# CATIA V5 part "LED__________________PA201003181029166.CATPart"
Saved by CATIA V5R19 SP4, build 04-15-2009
Part number: LED__________________PA201003181029166
Bounding box of the stored display mesh (mm): x -2.895 to 2.894, y -2.5 to 2.9, z -10 to 8.71
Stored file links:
  E:\CadInnWork\InWork\LED__________________PA201003181029166.CATPart
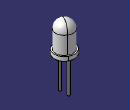
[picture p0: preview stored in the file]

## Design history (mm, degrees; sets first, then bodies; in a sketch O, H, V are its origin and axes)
Parameters
  Update = false
  PDM_version = "A"
  PDM_iteration = 1
  PDM_owner = "moren                    "
  PDM_comment = ""
  PDM_partnumber = "PA002170EA6A57201003181029160006"
Body1 (main body)
  Sketch1 on yz-plane, origin (0, 0, 0), H (0, 1, 0), V (0, 0, 1)
    axis line L1 (0, 64.2413) -> (0, -58.0007)
    point P1 (0, 64.2413)
    line L2 (0, 0) -> (2.9, 0)
    line L3 (2.9, 0) -> (2.9, 1.14)
    line L4 (2.9, 1.14) -> (2.5, 1.14)
    line L5 (2.5, 1.14) -> (2.5, 6.21)
    arc A1 centre (0, 6.21) radius 2.5 from (2.5, 6.21) to (0, 8.71) ccw
    point P7 (0, 6.21)
    point P8 (0, 8.71)
    "Radius" L3 L1 = 2.9
    "Radius" L5 L1 = 2.5
    length L3 = 1.14
    distance L2 P8 = 8.71
    coincidence: P1 V, P8 V, P7 L1
    vertical: L1 V, L3 V, L5 V
    horizontal: L2 H, L4 H
    tangency: A1 L5
  Shaft1: profile Sketch1, axis Sketch1.L1, angle 360
  Sketch2 on yz-plane, origin (0, 0, 0), H (0, 1, 0), V (0, 0, 1)
    line L1 (-4.2366, 3.4966) -> (-2.5, 3.4966)
    line L2 (-2.5, 3.4966) -> (-2.5, -3.9423)
    line L3 (-2.5, -3.9423) -> (-4.2366, -3.9423)
    line L4 (-4.2366, -3.9423) -> (-4.2366, 3.4966)
    reference intersected line E1 through (0, 0) direction (0, 1) from zx-plane
    distance E1 L2 = 2.5
    horizontal: L1 H, L3 H
    vertical: L2 V, L4 V
  Pocket1: profile Sketch2, direction (-1, 0, 0), length 20, mirrored extent
  Sketch3 on face of Shaft1 from Sketch1.L2, origin (0, 0, 0), H (1, 0, 0), V (0, -1, 0)
    line L1 (-0.25, 1.52) -> (0.25, 1.52)
    line L2 (0.25, 1.52) -> (0.25, 1.02)
    line L3 (0.25, 1.02) -> (-0.25, 1.02)
    line L4 (-0.25, 1.02) -> (-0.25, 1.52)
    construction line L5 (0, 1.7254) -> (0, -1.3591)
    reference intersected line E1 through (0, 0) direction (0, 1) from yz-plane
    construction line L6 (1.5543, 1.27) -> (-1.1509, 1.27)
    reference intersected line E2 through (0, 0) direction (1, 0) from zx-plane
    length L4 = 0.5
    length L1 = 0.5
    distance E2 L6 = 1.27
    horizontal: L1 H, L3 H, L6 H
    vertical: L2 V, L4 V, L5 V
    symmetry: L2 L4 L5, L2 L4 E1, L3 L1 L6
  Pad1: profile Sketch3, direction (0, 0, -1), length 10
  Mirror1: of Pad1, about zx-plane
